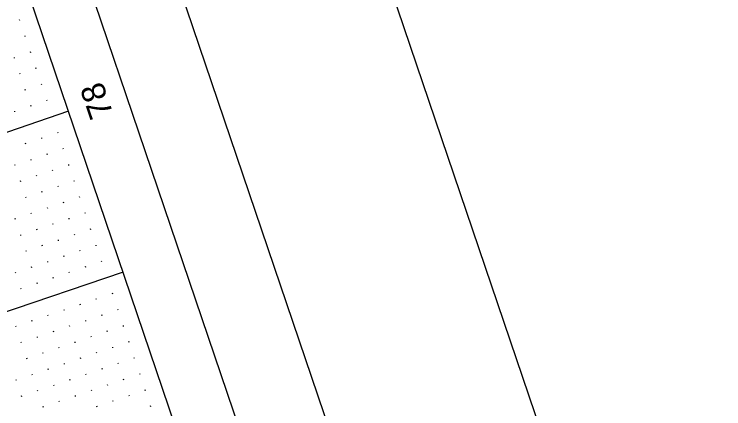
# Model space of a CAD drawing. Extents: x 2150800 to 2152547, y 141860 to 143950.
# Drawn here: x 2152172.8 to 2152381.5, y 142804.4 to 142920.5 of the extents above; entities that cross this region are included whole.
import ezdxf

# ---------------------------------------------------------------- set-up
doc = ezdxf.new("R2010")
doc.units = 0
for name, color, linetype in [('SHT_Plan_Profile_Sheet_Sta_Txt', 7, 'Continuous'), ('SHT_Plot_Shape_Full', 7, 'Continuous'), ('SHT_Plot_Shape_Half', 7, 'Continuous'), ('SHT_Profile_Grid_Major', 7, 'Continuous'), ('SHT_Profile_Grid_Minor', 7, 'Continuous'), ('SHT_Sheet_Border', 7, 'Continuous')]:
    doc.layers.add(name, color=color, linetype=linetype)

msp = doc.modelspace()

# ---------------------------------------------------------------- linework, layer by layer
at = {"layer": 'SHT_Plot_Shape_Full'}
msp.add_lwpolyline([(2151378.63, 141860.13), (2150800.36, 143564.71), (2151936.74, 143950.23), (2152515.02, 142245.65)], close=True, dxfattribs=at)
at = {"layer": 'SHT_Plot_Shape_Half'}
msp.add_lwpolyline([(2151391.39, 141950.92), (2150845.24, 143560.8), (2151886.93, 143914.19), (2152433.08, 142304.31)], close=True, dxfattribs=at)
at = {"layer": 'SHT_Profile_Grid_Major'}
for p, q in [((2152188.83, 142891.99), (2151715.33, 142731.36)), ((2152204.89, 142844.64), (2151731.4, 142684.01))]:
    msp.add_line(p, q, dxfattribs=at)
at = {"layer": 'SHT_Profile_Grid_Minor'}
for p, q in [((2152174.5, 142918.68), (2152174.42, 142918.91)), ((2152176.1, 142913.94), (2152176.02, 142914.18)), ((2152177.71, 142909.21), (2152177.63, 142909.44)), ((2152172.97, 142907.6), (2152172.89, 142907.84)), ((2152179.32, 142904.47), (2152179.24, 142904.71)), ((2152174.58, 142902.87), (2152174.5, 142903.1)), ((2152180.92, 142899.74), (2152180.84, 142899.97)), ((2152176.19, 142898.13), (2152176.11, 142898.37)), ((2152182.53, 142895), (2152182.45, 142895.24)), ((2152177.79, 142893.4), (2152177.71, 142893.63)), ((2152173.06, 142891.79), (2152172.98, 142892.03)), ((2152181.01, 142883.93), (2152180.93, 142884.16)), ((2152185.74, 142885.53), (2152185.66, 142885.77)), ((2152176.27, 142882.32), (2152176.19, 142882.56)), ((2152187.35, 142880.8), (2152187.27, 142881.03)), ((2152177.88, 142877.59), (2152177.8, 142877.82)), ((2152182.61, 142879.19), (2152182.53, 142879.43)), ((2152173.14, 142875.98), (2152173.06, 142876.22)), ((2152188.95, 142876.06), (2152188.87, 142876.3)), ((2152184.22, 142874.46), (2152184.14, 142874.69)), ((2152174.75, 142871.24), (2152174.67, 142871.48)), ((2152179.48, 142872.85), (2152179.4, 142873.09)), ((2152190.56, 142871.33), (2152190.48, 142871.56)), ((2152185.83, 142869.72), (2152185.74, 142869.96)), ((2152181.09, 142868.12), (2152181.01, 142868.35)), ((2152176.36, 142866.51), (2152176.27, 142866.75)), ((2152187.43, 142864.99), (2152187.35, 142865.22)), ((2152192.17, 142866.59), (2152192.09, 142866.83)), ((2152182.7, 142863.38), (2152182.62, 142863.62)), ((2152177.96, 142861.77), (2152177.88, 142862.01)), ((2152193.77, 142861.86), (2152193.69, 142862.09)), ((2152173.23, 142860.17), (2152173.15, 142860.4)), ((2152184.3, 142858.65), (2152184.22, 142858.88)), ((2152189.04, 142860.25), (2152188.96, 142860.49)), ((2152179.57, 142857.04), (2152179.49, 142857.28)), ((2152195.38, 142857.12), (2152195.3, 142857.36)), ((2152174.83, 142855.43), (2152174.75, 142855.67)), ((2152190.64, 142855.52), (2152190.56, 142855.75)), ((2152181.17, 142852.3), (2152181.09, 142852.54)), ((2152185.91, 142853.91), (2152185.83, 142854.15)), ((2152196.99, 142852.39), (2152196.9, 142852.63)), ((2152176.44, 142850.7), (2152176.36, 142850.93)), ((2152192.25, 142850.78), (2152192.17, 142851.02)), ((2152187.52, 142849.18), (2152187.44, 142849.41)), ((2152182.78, 142847.57), (2152182.7, 142847.81)), ((2152193.86, 142846.05), (2152193.78, 142846.28)), ((2152198.59, 142847.65), (2152198.51, 142847.89)), ((2152173.31, 142844.36), (2152173.23, 142844.59)), ((2152178.05, 142845.96), (2152177.97, 142846.2)), ((2152189.12, 142844.44), (2152189.04, 142844.68)), ((2152184.39, 142842.83), (2152184.31, 142843.07)), ((2152179.65, 142841.23), (2152179.57, 142841.46)), ((2152174.92, 142839.62), (2152174.84, 142839.86)), ((2152201.8, 142838.18), (2152201.72, 142838.42)), ((2152197.07, 142836.58), (2152196.99, 142836.81)), ((2152192.33, 142834.97), (2152192.25, 142835.21)), ((2152182.86, 142831.76), (2152182.78, 142831.99)), ((2152187.6, 142833.36), (2152187.52, 142833.6)), ((2152198.68, 142831.84), (2152198.6, 142832.08)), ((2152203.41, 142833.45), (2152203.33, 142833.69)), ((2152178.13, 142830.15), (2152178.05, 142830.39)), ((2152193.94, 142830.24), (2152193.86, 142830.47)), ((2152173.39, 142828.55), (2152173.31, 142828.78)), ((2152189.21, 142828.63), (2152189.13, 142828.87)), ((2152205.02, 142828.71), (2152204.94, 142828.95)), ((2152179.74, 142825.42), (2152179.66, 142825.65)), ((2152184.47, 142827.02), (2152184.39, 142827.26)), ((2152195.55, 142825.5), (2152195.47, 142825.74)), ((2152200.28, 142827.11), (2152200.2, 142827.34)), ((2152175, 142823.81), (2152174.92, 142824.05)), ((2152190.81, 142823.89), (2152190.73, 142824.13)), ((2152206.62, 142823.98), (2152206.54, 142824.22)), ((2152186.08, 142822.29), (2152186, 142822.53)), ((2152201.89, 142822.37), (2152201.81, 142822.61)), ((2152176.61, 142819.08), (2152176.53, 142819.31)), ((2152181.34, 142820.68), (2152181.26, 142820.92)), ((2152192.42, 142819.16), (2152192.34, 142819.4)), ((2152197.15, 142820.77), (2152197.07, 142821)), ((2152208.23, 142819.24), (2152208.15, 142819.48)), ((2152187.68, 142817.55), (2152187.6, 142817.79)), ((2152203.49, 142817.64), (2152203.41, 142817.87)), ((2152182.95, 142815.95), (2152182.87, 142816.18)), ((2152198.76, 142816.03), (2152198.68, 142816.27)), ((2152173.48, 142812.73), (2152173.4, 142812.97)), ((2152178.21, 142814.34), (2152178.13, 142814.58)), ((2152189.29, 142812.82), (2152189.21, 142813.06)), ((2152194.02, 142814.42), (2152193.94, 142814.66)), ((2152205.1, 142812.9), (2152205.02, 142813.14)), ((2152209.84, 142814.51), (2152209.76, 142814.75)), ((2152184.55, 142811.21), (2152184.47, 142811.45)), ((2152200.37, 142811.3), (2152200.29, 142811.53)), ((2152179.82, 142809.61), (2152179.74, 142809.84)), ((2152195.63, 142809.69), (2152195.55, 142809.93)), ((2152211.44, 142809.77), (2152211.36, 142810.01)), ((2152175.08, 142808), (2152175, 142808.24)), ((2152186.16, 142806.48), (2152186.08, 142806.71)), ((2152190.9, 142808.08), (2152190.82, 142808.32)), ((2152201.97, 142806.56), (2152201.89, 142806.8)), ((2152206.71, 142808.17), (2152206.63, 142808.4)), ((2152181.43, 142804.87), (2152181.35, 142805.11)), ((2152197.24, 142804.95), (2152197.16, 142805.19)), ((2152213.05, 142805.04), (2152212.97, 142805.28))]:
    msp.add_line(p, q, dxfattribs=at)
at = {"layer": 'SHT_Sheet_Border'}
msp.add_line((2152361.51, 142382.99), (2151939.85, 143625.91), dxfattribs=at)
msp.add_lwpolyline([(2151383.74, 142051.28), (2150877.75, 143542.79), (2151872.09, 143880.12), (2152378.08, 142388.61)], close=True, dxfattribs=at)

# ---------------------------------------------------------------- texts
at = {"layer": 'SHT_Plan_Profile_Sheet_Sta_Txt'}
msp.add_text('78', height=7, rotation=108.7393, dxfattribs=at).set_placement((2152202.04, 142891.19))

doc.saveas('drawing.dxf')
